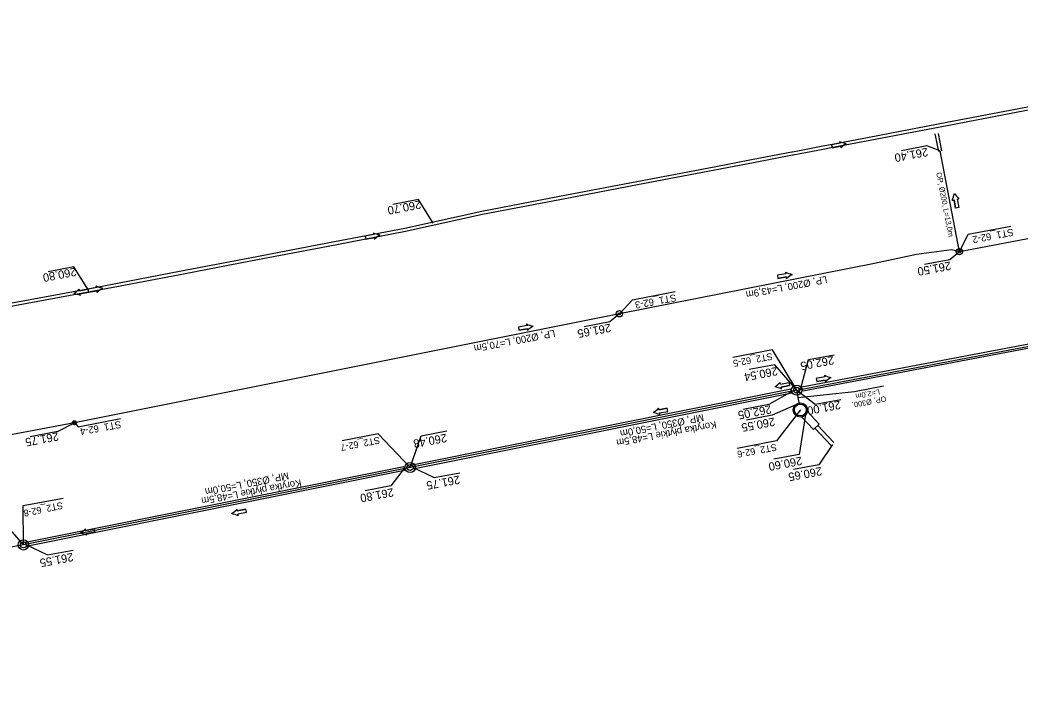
# Model space of a CAD drawing. Extents: x -1 to 65640748, y -22 to 5530284.
# Drawn here: x 6556797.5 to 6556924.3, y 5528523.2 to 5528610.2 of the extents above; entities that cross this region are included whole.
import ezdxf

# ---------------------------------------------------------------- set-up
doc = ezdxf.new("R2010")
doc.units = 0
for name, color, linetype in [('TOR_PROF-studnie i osadniki', 7, 'Continuous'), ('TOR_PS_ODW-drenaze', 7, 'Continuous'), ('TOR_PS_ODW-drenokolektory', 7, 'Continuous'), ('TOR_PS_ODW-kolektory', 7, 'Continuous'), ('TOR_PS_ODW-studnie PEHD', 7, 'Continuous'), ('TOR_PS_OPIS_O-opisy rurociagow', 7, 'Continuous'), ('TOR_PS_OPIS_O-opisy studni', 7, 'Continuous'), ('TOR_PS_OPIS_T-INFO', 7, 'Continuous'), ('TOR_PS_T-rowy otwarte umocnione', 7, 'Continuous')]:
    doc.layers.add(name, color=color, linetype=linetype)

msp = doc.modelspace()

# ---------------------------------------------------------------- linework, layer by layer
at = {"layer": 'TOR_PROF-studnie i osadniki'}
msp.add_lwpolyline([(6556896.64, 5528559.86), (6556898.14, 5528558.26), (6556898.87, 5528558.95), (6556897.37, 5528560.55)], dxfattribs=at)
for centre, radius in [((6556896.02, 5528563.25), 0.65), ((6556896.02, 5528563.25), 0.375), ((6556896.49, 5528560.75), 0.9), ((6556896.49, 5528560.75), 0.75), ((6556804.42, 5528559.12), 0.25), ((6556804.42, 5528559.12), 0.125), ((6556846.99, 5528553.45), 0.65), ((6556846.99, 5528553.45), 0.375), ((6556797.95, 5528543.64), 0.65), ((6556797.95, 5528543.64), 0.375)]:
    msp.add_circle(centre, radius, dxfattribs=at)
at = {"layer": 'TOR_PS_ODW-drenaze'}
for points in [[(6556953.82, 5528587.85), (6556916.67, 5528580.8), (6556916.67, 5528580.8)], [(6556896.02, 5528563.25), (6556950.06, 5528573.49)]]:
    msp.add_lwpolyline(points, dxfattribs=at)
at = {"layer": 'TOR_PS_ODW-drenokolektory'}
for p, q in [((6556914.03, 5528593.51), (6556913.6, 5528595.73)), ((6556914.41, 5528593.57), (6556913.99, 5528595.8))]:
    msp.add_line(p, q, dxfattribs=at)
for points in [[(6556916.67, 5528580.8), (6556914.23, 5528593.58)], [(6556916.67, 5528580.8), (6556915.66, 5528581.03), (6556911.22, 5528580.44), (6556905.89, 5528579.31), (6556873.53, 5528572.93)], [(6556873.53, 5528572.93), (6556804.42, 5528559.12)], [(6556896.02, 5528563.25), (6556846.99, 5528553.45), (6556797.95, 5528543.64), (6556748.83, 5528534.33), (6556692.92, 5528523.23)], [(6556896.02, 5528563.25), (6556846.99, 5528553.45), (6556797.95, 5528543.64), (6556748.83, 5528534.33)], [(6556896.02, 5528563.25), (6556846.99, 5528553.45), (6556797.95, 5528543.64)], [(6556896.02, 5528563.25), (6556846.99, 5528553.45)], [(6556804.42, 5528559.12), (6556766.01, 5528551.9), (6556757.4, 5528549.85), (6556755.29, 5528549.81)]]:
    msp.add_lwpolyline(points, dxfattribs=at)
at = {"layer": 'TOR_PS_ODW-kolektory'}
for points in [[(6556916.67, 5528580.8), (6556914.23, 5528593.58)], [(6556916.67, 5528580.8), (6556914.23, 5528593.58)], [(6556896.37, 5528561.42), (6556896.02, 5528563.25)]]:
    msp.add_lwpolyline(points, dxfattribs=at)
at = {"layer": 'TOR_PS_ODW-studnie PEHD'}
for centre, radius in [((6556916.65, 5528580.8), 0.4), ((6556916.65, 5528580.8), 0.145), ((6556873.53, 5528572.93), 0.4), ((6556873.53, 5528572.93), 0.145), ((6556804.42, 5528559.12), 0.25), ((6556804.42, 5528559.12), 0.112)]:
    msp.add_circle(centre, radius, dxfattribs=at)
at = {"layer": 'TOR_PS_OPIS_O-opisy rurociagow'}
for p, q in [((6556901.52, 5528594.57), (6556900.44, 5528594.36)), ((6556901.52, 5528594.57), (6556900.44, 5528594.36)), ((6556900.44, 5528594.36), (6556900.52, 5528593.97)), ((6556900.44, 5528594.36), (6556900.52, 5528593.97)), ((6556900.52, 5528593.97), (6556901.59, 5528594.17)), ((6556901.59, 5528594.17), (6556900.52, 5528593.97)), ((6556916.17, 5528586.31), (6556915.97, 5528587.39)), ((6556915.97, 5528587.39), (6556916.17, 5528586.31)), ((6556916.36, 5528587.46), (6556916.57, 5528586.39)), ((6556916.36, 5528587.46), (6556916.57, 5528586.39)), ((6556916.57, 5528586.39), (6556916.17, 5528586.31)), ((6556916.57, 5528586.39), (6556916.17, 5528586.31)), ((6556842.38, 5528582.99), (6556841.31, 5528582.78)), ((6556842.38, 5528582.99), (6556841.31, 5528582.78)), ((6556841.31, 5528582.78), (6556841.38, 5528582.39)), ((6556841.31, 5528582.78), (6556841.38, 5528582.39)), ((6556841.38, 5528582.39), (6556842.46, 5528582.6)), ((6556842.46, 5528582.6), (6556841.38, 5528582.39)), ((6556894.64, 5528577.99), (6556893.57, 5528577.81)), ((6556894.64, 5528577.99), (6556893.57, 5528577.81)), ((6556893.57, 5528577.81), (6556893.63, 5528577.41)), ((6556893.57, 5528577.81), (6556893.63, 5528577.41)), ((6556893.63, 5528577.41), (6556894.71, 5528577.6)), ((6556894.71, 5528577.6), (6556893.63, 5528577.41)), ((6556805.06, 5528575.85), (6556806.14, 5528576.05)), ((6556805.06, 5528575.85), (6556806.14, 5528576.05)), ((6556807.21, 5528576.26), (6556806.14, 5528576.05)), ((6556807.21, 5528576.26), (6556806.14, 5528576.05)), ((6556806.14, 5528576.05), (6556806.21, 5528575.66)), ((6556806.14, 5528576.05), (6556806.21, 5528575.66)), ((6556806.14, 5528576.05), (6556806.21, 5528575.66)), ((6556806.14, 5528576.05), (6556806.21, 5528575.66)), ((6556806.21, 5528575.66), (6556807.28, 5528575.86)), ((6556807.28, 5528575.86), (6556806.21, 5528575.66)), ((6556806.21, 5528575.66), (6556805.14, 5528575.46)), ((6556805.14, 5528575.46), (6556806.21, 5528575.66)), ((6556861.8, 5528571.43), (6556860.73, 5528571.24)), ((6556861.8, 5528571.43), (6556860.73, 5528571.24)), ((6556860.73, 5528571.24), (6556860.79, 5528570.85)), ((6556860.73, 5528571.24), (6556860.79, 5528570.85)), ((6556860.79, 5528570.85), (6556861.87, 5528571.03)), ((6556861.87, 5528571.03), (6556860.79, 5528570.85)), ((6556899.58, 5528564.93), (6556898.5, 5528564.74)), ((6556899.58, 5528564.93), (6556898.5, 5528564.74)), ((6556898.5, 5528564.74), (6556898.57, 5528564.35)), ((6556898.5, 5528564.74), (6556898.57, 5528564.35)), ((6556898.57, 5528564.35), (6556899.65, 5528564.54)), ((6556899.65, 5528564.54), (6556898.57, 5528564.35)), ((6556893.95, 5528564.02), (6556895.02, 5528564.23)), ((6556893.95, 5528564.02), (6556895.02, 5528564.23)), ((6556895.1, 5528563.84), (6556894.03, 5528563.62)), ((6556894.03, 5528563.62), (6556895.1, 5528563.84)), ((6556895.02, 5528564.23), (6556895.1, 5528563.84)), ((6556895.02, 5528564.23), (6556895.1, 5528563.84)), ((6556879.61, 5528560.97), (6556878.54, 5528560.76)), ((6556878.54, 5528560.76), (6556879.61, 5528560.97)), ((6556879.69, 5528560.57), (6556879.61, 5528560.97)), ((6556879.69, 5528560.57), (6556879.61, 5528560.97)), ((6556878.62, 5528560.36), (6556879.69, 5528560.57)), ((6556878.62, 5528560.36), (6556879.69, 5528560.57)), ((6556826.15, 5528548.16), (6556825.08, 5528547.95)), ((6556825.08, 5528547.95), (6556826.15, 5528548.16)), ((6556826.23, 5528547.77), (6556826.15, 5528548.16)), ((6556826.23, 5528547.77), (6556826.15, 5528548.16)), ((6556825.15, 5528547.56), (6556826.23, 5528547.77)), ((6556825.15, 5528547.56), (6556826.23, 5528547.77)), ((6556806.92, 5528545.67), (6556805.85, 5528545.47)), ((6556805.85, 5528545.47), (6556806.92, 5528545.67)), ((6556807, 5528545.28), (6556806.92, 5528545.67)), ((6556807, 5528545.28), (6556806.92, 5528545.67)), ((6556805.93, 5528545.07), (6556807, 5528545.28)), ((6556805.93, 5528545.07), (6556807, 5528545.28))]:
    msp.add_line(p, q, dxfattribs=at)
for points in [[(6556901.46, 5528594.79), (6556901.46, 5528594.79)], [(6556901.62, 5528593.95), (6556901.62, 5528593.95)], [(6556915.75, 5528587.34), (6556915.75, 5528587.34)], [(6556916.59, 5528587.49), (6556916.59, 5528587.49)], [(6556842.33, 5528583.21), (6556842.33, 5528583.21)], [(6556842.49, 5528582.37), (6556842.49, 5528582.37)], [(6556894.59, 5528578.21), (6556894.59, 5528578.21)], [(6556894.74, 5528577.38), (6556894.74, 5528577.38)], [(6556805.03, 5528576.07), (6556805.03, 5528576.07)], [(6556807.16, 5528576.47), (6556807.16, 5528576.47)], [(6556805.19, 5528575.24), (6556805.19, 5528575.24)], [(6556807.32, 5528575.64), (6556807.32, 5528575.64)], [(6556861.75, 5528571.65), (6556861.75, 5528571.65)], [(6556861.9, 5528570.81), (6556861.9, 5528570.81)], [(6556899.53, 5528565.15), (6556899.53, 5528565.15)], [(6556893.92, 5528564.24), (6556893.92, 5528564.24)], [(6556894.09, 5528563.41), (6556894.09, 5528563.41)], [(6556899.68, 5528564.31), (6556899.68, 5528564.31)], [(6556878.51, 5528560.98), (6556878.51, 5528560.98)], [(6556878.67, 5528560.15), (6556878.67, 5528560.15)], [(6556825.04, 5528548.17), (6556825.04, 5528548.17)], [(6556825.21, 5528547.34), (6556825.21, 5528547.34)], [(6556805.82, 5528545.69), (6556805.82, 5528545.69)], [(6556805.98, 5528544.85), (6556805.98, 5528544.85)]]:
    msp.add_lwpolyline(points, dxfattribs=at)
for centre, radius, start, end in [((6556903.38, 5528599.32), 4.92, 247.1079, 257.4898), ((6556901.92, 5528594.78), 0.458, 179.2225, 207.6838), ((6556903.38, 5528599.32), 4.92, 247.1079, 257.4898), ((6556901.92, 5528594.78), 0.458, 179.2225, 207.6838), ((6556902.05, 5528594.13), 0.458, 173.9519, 202.4131), ((6556902.05, 5528594.13), 0.458, 173.9519, 202.4131), ((6556905.07, 5528590.45), 4.92, 124.1458, 134.5277), ((6556905.07, 5528590.45), 4.92, 124.1458, 134.5277), ((6556911.22, 5528589.25), 4.92, 337.0234, 347.4052), ((6556911.22, 5528589.25), 4.92, 337.0234, 347.4052), ((6556915.76, 5528587.79), 0.458, 269.1379, 297.5992), ((6556915.76, 5528587.79), 0.458, 269.1379, 297.5992), ((6556920.1, 5528590.94), 4.92, 214.0613, 224.4431), ((6556920.1, 5528590.94), 4.92, 214.0613, 224.4431), ((6556916.41, 5528587.92), 0.458, 263.8673, 292.3285), ((6556916.41, 5528587.92), 0.458, 263.8673, 292.3285), ((6556844.24, 5528587.74), 4.92, 247.1079, 257.4898), ((6556842.79, 5528583.2), 0.458, 179.2225, 207.6838), ((6556844.24, 5528587.74), 4.92, 247.1079, 257.4898), ((6556842.79, 5528583.2), 0.458, 179.2225, 207.6838), ((6556842.91, 5528582.55), 0.458, 173.9519, 202.4131), ((6556842.91, 5528582.55), 0.458, 173.9519, 202.4131), ((6556845.94, 5528578.87), 4.92, 124.1458, 134.5277), ((6556845.94, 5528578.87), 4.92, 124.1458, 134.5277), ((6556896.58, 5528582.71), 4.92, 246.1449, 256.5268), ((6556895.05, 5528578.2), 0.458, 178.2595, 206.7208), ((6556896.58, 5528582.71), 4.92, 246.1449, 256.5268), ((6556895.05, 5528578.2), 0.458, 178.2595, 206.7208), ((6556895.16, 5528577.54), 0.458, 172.9889, 201.4501), ((6556895.16, 5528577.54), 0.458, 172.9889, 201.4501), ((6556898.13, 5528573.81), 4.92, 123.1828, 133.5647), ((6556898.13, 5528573.81), 4.92, 123.1828, 133.5647), ((6556801.59, 5528579.59), 4.92, 303.9767, 314.3585), ((6556801.59, 5528579.59), 4.92, 303.9767, 314.3585), ((6556804.61, 5528575.9), 0.458, 353.7827, 22.244), ((6556804.61, 5528575.9), 0.458, 353.7827, 22.244), ((6556809.07, 5528581), 4.92, 247.1079, 257.4898), ((6556807.62, 5528576.47), 0.458, 179.2225, 207.6838), ((6556809.07, 5528581), 4.92, 247.1079, 257.4898), ((6556807.62, 5528576.47), 0.458, 179.2225, 207.6838), ((6556807.74, 5528575.81), 0.458, 173.9519, 202.4131), ((6556807.74, 5528575.81), 0.458, 173.9519, 202.4131), ((6556810.77, 5528572.13), 4.92, 124.1458, 134.5277), ((6556810.77, 5528572.13), 4.92, 124.1458, 134.5277), ((6556803.26, 5528570.71), 4.92, 66.9388, 77.3206), ((6556803.26, 5528570.71), 4.92, 66.9388, 77.3206), ((6556804.73, 5528575.24), 0.458, 359.0534, 27.5146), ((6556804.73, 5528575.24), 0.458, 359.0534, 27.5146), ((6556863.74, 5528576.14), 4.92, 246.1449, 256.5268), ((6556862.21, 5528571.63), 0.458, 178.2595, 206.7208), ((6556863.74, 5528576.14), 4.92, 246.1449, 256.5268), ((6556862.21, 5528571.63), 0.458, 178.2595, 206.7208), ((6556862.32, 5528570.98), 0.458, 172.9889, 201.4501), ((6556862.32, 5528570.98), 0.458, 172.9889, 201.4501), ((6556865.29, 5528567.25), 4.92, 123.1828, 133.5647), ((6556865.29, 5528567.25), 4.92, 123.1828, 133.5647), ((6556901.52, 5528569.65), 4.92, 246.1449, 256.5268), ((6556899.99, 5528565.14), 0.458, 178.2595, 206.7208), ((6556901.52, 5528569.65), 4.92, 246.1449, 256.5268), ((6556899.99, 5528565.14), 0.458, 178.2595, 206.7208), ((6556900.1, 5528564.48), 0.458, 172.9889, 201.4501), ((6556900.1, 5528564.48), 0.458, 172.9889, 201.4501), ((6556903.06, 5528560.75), 4.92, 123.1828, 133.5647), ((6556903.06, 5528560.75), 4.92, 123.1828, 133.5647), ((6556890.42, 5528567.7), 4.92, 304.9397, 315.3215), ((6556890.42, 5528567.7), 4.92, 304.9397, 315.3215), ((6556892.24, 5528558.85), 4.92, 67.9018, 78.2836), ((6556892.24, 5528558.85), 4.92, 67.9018, 78.2836), ((6556893.49, 5528564.06), 0.458, 354.7457, 23.207), ((6556893.49, 5528564.06), 0.458, 354.7457, 23.207), ((6556893.63, 5528563.4), 0.458, 0.0164, 28.4776), ((6556893.63, 5528563.4), 0.458, 0.0164, 28.4776), ((6556875.05, 5528564.47), 4.92, 304.3278, 314.7097), ((6556875.05, 5528564.47), 4.92, 304.3278, 314.7097), ((6556878.08, 5528560.8), 0.458, 354.1339, 22.5951), ((6556878.08, 5528560.8), 0.458, 354.1339, 22.5951), ((6556876.77, 5528555.61), 4.92, 67.2899, 77.6718), ((6556876.77, 5528555.61), 4.92, 67.2899, 77.6718), ((6556878.21, 5528560.15), 0.458, 359.4045, 27.8657), ((6556878.21, 5528560.15), 0.458, 359.4045, 27.8657), ((6556821.59, 5528551.67), 4.92, 304.3278, 314.7097), ((6556821.59, 5528551.67), 4.92, 304.3278, 314.7097), ((6556824.62, 5528548), 0.458, 354.1339, 22.5951), ((6556824.62, 5528548), 0.458, 354.1339, 22.5951), ((6556823.31, 5528542.8), 4.92, 67.2899, 77.6718), ((6556823.31, 5528542.8), 4.92, 67.2899, 77.6718), ((6556824.75, 5528547.34), 0.458, 359.4045, 27.8657), ((6556824.75, 5528547.34), 0.458, 359.4045, 27.8657), ((6556802.36, 5528549.18), 4.92, 304.3335, 314.7153), ((6556802.36, 5528549.18), 4.92, 304.3335, 314.7153), ((6556805.39, 5528545.51), 0.458, 354.1395, 22.6007), ((6556805.39, 5528545.51), 0.458, 354.1395, 22.6007), ((6556804.08, 5528540.32), 4.92, 67.2956, 77.6774), ((6556804.08, 5528540.32), 4.92, 67.2956, 77.6774), ((6556805.52, 5528544.86), 0.458, 359.4101, 27.8714), ((6556805.52, 5528544.86), 0.458, 359.4101, 27.8714)]:
    msp.add_arc(centre, radius, start, end, dxfattribs=at)
at = {"layer": 'TOR_PS_OPIS_T-INFO'}
for points in [[(6556914.23, 5528593.58), (6556912.53, 5528594.21), (6556909.3, 5528593.58)], [(6556849.94, 5528584.44), (6556848.05, 5528587.41), (6556844.82, 5528586.79)], [(6556916.65, 5528580.8), (6556917.78, 5528583.03), (6556923.17, 5528584.06)], [(6556916.65, 5528580.8), (6556915.44, 5528579.78), (6556912.21, 5528579.16)], [(6556806.23, 5528575.91), (6556804.34, 5528578.88), (6556801.11, 5528578.26)], [(6556873.53, 5528572.93), (6556875.21, 5528574.72), (6556880.6, 5528575.75)], [(6556873.53, 5528572.93), (6556872.32, 5528571.91), (6556869.09, 5528571.29)], [(6556896.02, 5528563.25), (6556892.94, 5528568.35), (6556887.94, 5528567.39)], [(6556896.49, 5528563.34), (6556897.53, 5528567.13), (6556900.77, 5528567.74)], [(6556896.02, 5528563.25), (6556893.23, 5528566.48), (6556890, 5528565.86)], [(6556896.02, 5528563.25), (6556898.38, 5528561.48), (6556901.62, 5528562.08)], [(6556896.19, 5528562.34), (6556903.36, 5528563.1), (6556907.03, 5528563.79)], [(6556895.49, 5528563.14), (6556892.48, 5528561.45), (6556889.24, 5528560.82)], [(6556896.49, 5528560.75), (6556893.47, 5528556.84), (6556888.47, 5528555.87)], [(6556896.29, 5528561.56), (6556892.89, 5528560.07), (6556889.65, 5528559.44)], [(6556804.49, 5528559.11), (6556804.89, 5528558.62), (6556810.27, 5528559.65)], [(6556897.13, 5528560.15), (6556896.33, 5528555.12), (6556893.1, 5528554.5)], [(6556804.49, 5528559.11), (6556802.32, 5528558.02), (6556798.83, 5528557.36)], [(6556846.99, 5528553.45), (6556848.4, 5528557.47), (6556851.64, 5528558.08)], [(6556846.99, 5528553.45), (6556842.96, 5528557.71), (6556838.37, 5528556.82)], [(6556900.54, 5528556.38), (6556898.84, 5528553.81), (6556895.61, 5528553.18)], [(6556846.25, 5528553.31), (6556844.54, 5528551.14), (6556841.31, 5528550.51)], [(6556847.39, 5528553.46), (6556850.06, 5528552.18), (6556853.3, 5528552.78)], [(6556797.95, 5528543.64), (6556797.92, 5528548.62), (6556803.02, 5528549.57)], [(6556797.95, 5528543.64), (6556795.17, 5528546.87), (6556791.93, 5528546.25)], [(6556798.36, 5528543.66), (6556801.03, 5528542.38), (6556804.27, 5528542.98)]]:
    msp.add_lwpolyline(points, dxfattribs=at)
at = {"layer": 'TOR_PS_T-rowy otwarte umocnione'}
for p, q in [((6556949.7, 5528573.68), (6556896.68, 5528563.63)), ((6556895.39, 5528562.87), (6556847.34, 5528553.26)), ((6556900.38, 5528556.25), (6556898.33, 5528558.45)), ((6556900.75, 5528556.6), (6556898.7, 5528558.79)), ((6556846.2, 5528553.54), (6556798.21, 5528543.95))]:
    msp.add_line(p, q, dxfattribs=at)
for points in [[(6556983.12, 5528610.17), (6556973.97, 5528608.42), (6556964.15, 5528606.54), (6556954.33, 5528604.67), (6556944.5, 5528602.79), (6556934.68, 5528600.92), (6556924.86, 5528599.04), (6556915.04, 5528597.16), (6556905.21, 5528595.29), (6556900.3, 5528594.35), (6556899.32, 5528594.16), (6556896.37, 5528593.6), (6556895.49, 5528593.43), (6556895.39, 5528593.41), (6556890.48, 5528592.47), (6556885.57, 5528591.53), (6556875.75, 5528589.66), (6556865.92, 5528587.78), (6556856.1, 5528585.91)], [(6556983.38, 5528609.81), (6556974.05, 5528608.03), (6556964.22, 5528606.15), (6556954.4, 5528604.27), (6556944.58, 5528602.4), (6556934.76, 5528600.52), (6556924.93, 5528598.65), (6556915.11, 5528596.77), (6556905.29, 5528594.89), (6556900.38, 5528593.96), (6556899.39, 5528593.77), (6556896.45, 5528593.2), (6556895.56, 5528593.04), (6556895.47, 5528593.02), (6556890.55, 5528592.08), (6556885.64, 5528591.14), (6556875.82, 5528589.26), (6556866, 5528587.39), (6556856.18, 5528585.51)], [(6556856.1, 5528585.91), (6556846.33, 5528583.75), (6556836.51, 5528581.87), (6556826.69, 5528579.99), (6556816.87, 5528578.11), (6556807.04, 5528576.24), (6556797.21, 5528574.42), (6556787.37, 5528572.62), (6556777.54, 5528570.81), (6556767.7, 5528569), (6556757.87, 5528567.19), (6556748.03, 5528565.38), (6556738.2, 5528563.57), (6556728.36, 5528561.77), (6556718.53, 5528559.96), (6556708.69, 5528558.15), (6556698.86, 5528556.34), (6556689.02, 5528554.53), (6556683.31, 5528553.46)], [(6556856.18, 5528585.51), (6556846.41, 5528583.35), (6556836.59, 5528581.48), (6556826.76, 5528579.6), (6556816.94, 5528577.72), (6556807.12, 5528575.84), (6556797.28, 5528574.03), (6556787.45, 5528572.22), (6556777.61, 5528570.42), (6556767.78, 5528568.61), (6556757.94, 5528566.8), (6556748.11, 5528564.99), (6556738.27, 5528563.18), (6556728.44, 5528561.37), (6556718.6, 5528559.57), (6556708.77, 5528557.76), (6556698.93, 5528555.95), (6556689.1, 5528554.14), (6556683.68, 5528553.12)], [(6556949.8, 5528573.19), (6556896.78, 5528563.14), (6556896.69, 5528563.63)], [(6556895.38, 5528562.89), (6556895.28, 5528563.36), (6556847.24, 5528553.75)], [(6556846.2, 5528553.54), (6556846.3, 5528553.06), (6556798.31, 5528543.46)]]:
    msp.add_lwpolyline(points, dxfattribs=at)

# ---------------------------------------------------------------- texts
at = {"layer": 'TOR_PS_OPIS_O-opisy rurociagow'}
for s, height, rotation, p in [('OP, Ø200, L=13,0m', 0.675, 280.821, (6556913.72, 5528590.8)), ('LP, Ø200, L=43,9m', 0.9, 190.9157, (6556899.79, 5528577.74)), ('LP, Ø200, L=70,5m', 0.9, 190.9157, (6556865.3, 5528570.92)), ('L=2,0m', 0.675, 190.821, (6556906.5, 5528563.38)), ('OP, Ø300, ', 0.675, 190.821, (6556907.31, 5528562.51)), ('MP, Ø350, L=50,0m', 0.9, 191.184, (6556884.15, 5528560.25)), ('Korytka płytkie L=48,5m', 0.9, 190.3457, (6556885.76, 5528559.32)), ('Korytka płytkie L=48,5m', 0.9, 190.3457, (6556833.13, 5528551.94)), ('MP, Ø350, L=50,0m', 0.9, 191.184, (6556831.52, 5528552.87))]:
    msp.add_text(s, height=height, rotation=rotation, dxfattribs=at).set_placement(p)
at = {"layer": 'TOR_PS_OPIS_O-opisy studni'}
for s, height, rotation, p in [('ST1_62-2', 0.9, 190.942, (6556923.43, 5528583.74)), ('ST1_62-3', 0.9, 190.6615, (6556880.65, 5528575.43)), ('ST2_62-5', 0.863, 190.593, (6556892.87, 5528567.98)), ('ST1_62-4', 0.9, 190.4449, (6556810.27, 5528559.37)), ('ST2_62-7', 0.862, 190.9869, (6556843.08, 5528557.35)), ('ST2_62-6', 0.863, 190.593, (6556893.4, 5528556.46)), ('ST2_62-8', 0.862, 192.0076, (6556802.86, 5528549.09))]:
    msp.add_text(s, height=height, rotation=rotation, dxfattribs=at).set_placement(p)
at = {"layer": 'TOR_PS_OPIS_T-INFO'}
for s, rotation, p in [('261.40', 190.7159, (6556912.57, 5528593.98)), ('260.70', 190.7159, (6556848.28, 5528587.32)), ('260.80', 190.7159, (6556804.57, 5528578.79)), ('261.50', 190.7159, (6556915.48, 5528579.56)), ('261.65', 190.7159, (6556872.36, 5528571.69)), ('262.05', 190.7506, (6556900.64, 5528567.59)), ('260.54', 190.7159, (6556893.5, 5528566.2)), ('261.00', 190.7506, (6556901.49, 5528561.93)), ('262.05', 190.7159, (6556892.71, 5528561.36)), ('260.55', 190.7159, (6556893.16, 5528559.79)), ('261.75', 190.7159, (6556802.33, 5528557.93)), ('260.48', 190.7506, (6556851.55, 5528557.74)), ('260.60', 190.7159, (6556896.6, 5528554.84)), ('260.65', 190.7159, (6556899.11, 5528553.53)), ('261.75', 190.7506, (6556853.21, 5528552.45)), ('261.80', 190.7159, (6556844.81, 5528550.85)), ('261.55', 190.7506, (6556804.18, 5528542.64))]:
    msp.add_text(s, height=1.05, rotation=rotation, dxfattribs=at).set_placement(p)

doc.saveas('drawing.dxf')
